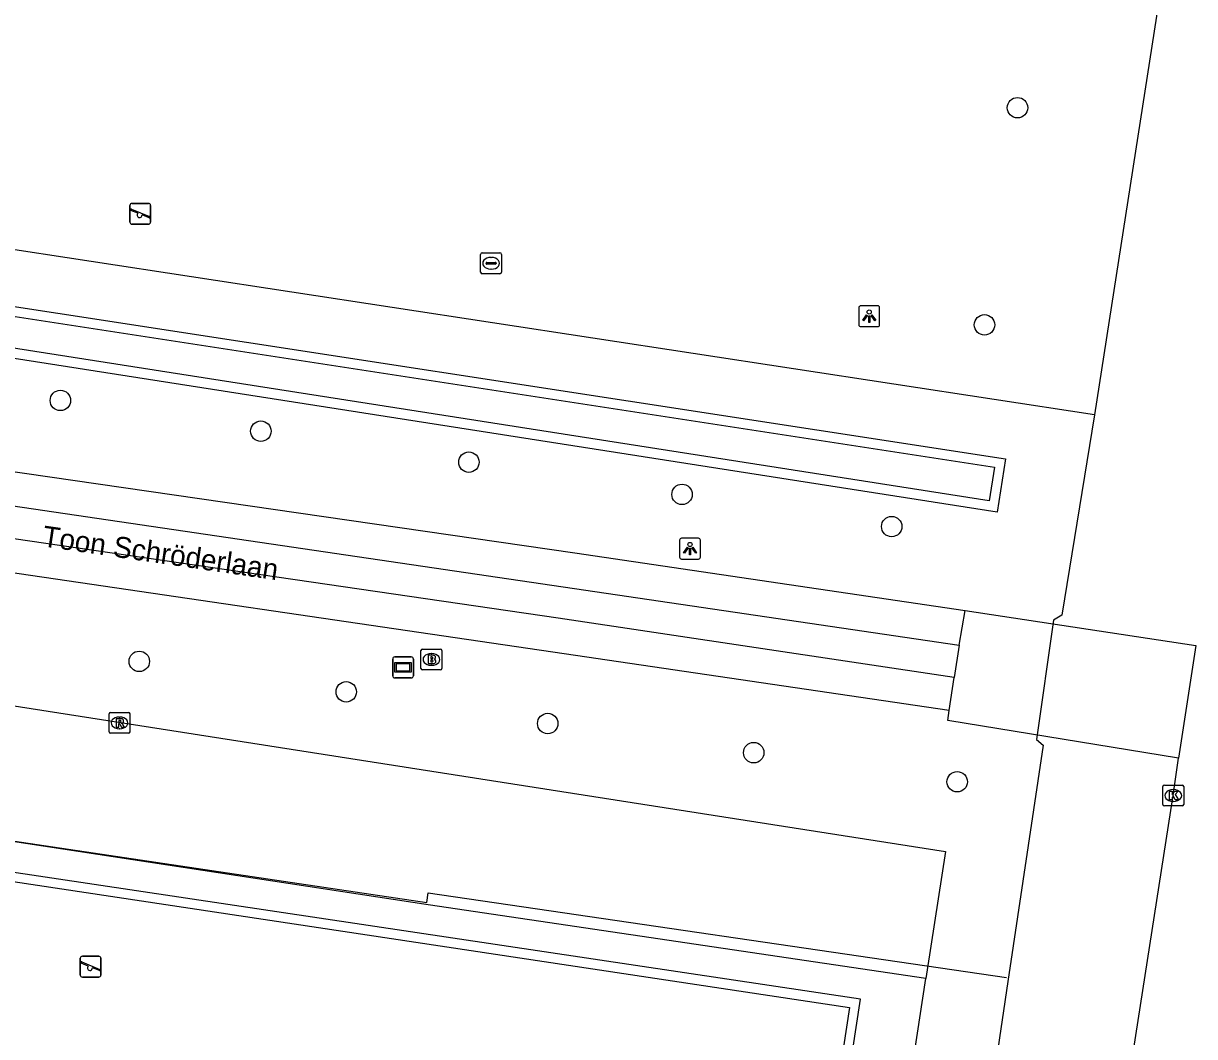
# Model space of a CAD drawing. Extents: x 161094 to 161705, y 379509 to 380907.
# Drawn here: x 161507.4 to 161563.4, y 380124 to 380172.4 of the extents above; entities that cross this region are included whole.
import ezdxf

# ---------------------------------------------------------------- set-up
doc = ezdxf.new("R2010")
doc.units = 0
for name, color, linetype in [('IMGEO_Boom', 7, 'Continuous'), ('IMGEO_Brandkraan', 7, 'Continuous'), ('IMGEO_Greppel_droge_sloot', 7, 'Continuous'), ('IMGEO_Groenvoorziening', 7, 'Continuous'), ('IMGEO_Hek', 7, 'Continuous'), ('IMGEO_Kolk', 7, 'Continuous'), ('IMGEO_Lichtpunt', 7, 'Continuous'), ('IMGEO_Openbare_ruimte_label', 7, 'Continuous'), ('IMGEO_OVBaan_gesloten', 7, 'Continuous'), ('IMGEO_Rijbaan_lokaal_gesloten', 7, 'Continuous'), ('IMGEO_Rijbaan_lokaal_open', 7, 'Continuous'), ('IMGEO_Rioolput', 7, 'Continuous'), ('IMGEO_Speelvoorziening', 7, 'Continuous'), ('IMGEO_Verklikker', 7, 'Continuous'), ('IMGEO_Voetpad_open', 7, 'Continuous'), ('IMGEO_Waterleidingput', 7, 'Continuous')]:
    doc.layers.add(name, color=color, linetype=linetype)

msp = doc.modelspace()

# ---------------------------------------------------------------- linework, layer by layer
at = {"layer": 'IMGEO_Boom'}
for centre in [(161554.975, 380168.413), (161553.395, 380158.024), (161509.163, 380154.409), (161518.76, 380152.937), (161528.716, 380151.457), (161538.917, 380149.914), (161548.952, 380148.375), (161512.94, 380141.927), (161522.845, 380140.47), (161532.489, 380138.953), (161542.348, 380137.559), (161552.088, 380136.168)]:
    msp.add_circle(centre, 0.489, dxfattribs=at)
at = {"layer": 'IMGEO_Brandkraan'}
for p, q in [((161526.422, 380141.592), (161526.422, 380142.444)), ((161526.497, 380142.518), (161527.349, 380142.518)), ((161526.91, 380142.298), (161526.935, 380142.298)), ((161527.423, 380142.444), (161527.423, 380141.592)), ((161526.933, 380141.738), (161526.908, 380141.738)), ((161527.349, 380141.518), (161526.497, 380141.518))]:
    msp.add_line(p, q, dxfattribs=at)
for points in [[(161526.422, 380141.592), (161526.422, 380142.444)], [(161526.497, 380142.518), (161527.349, 380142.518)], [(161527.423, 380142.444), (161527.423, 380141.592)], [(161526.77, 380142.218), (161526.77, 380141.818), (161526.983, 380141.818)], [(161527.001, 380142.218), (161526.77, 380142.218)], [(161526.949, 380142.137), (161526.895, 380142.137), (161526.895, 380142.061)], [(161526.895, 380142.061), (161526.948, 380142.061)], [(161526.957, 380141.985), (161526.895, 380141.985), (161526.895, 380141.904)], [(161526.895, 380141.904), (161526.957, 380141.904)], [(161527.349, 380141.518), (161526.497, 380141.518)]]:
    msp.add_lwpolyline(points, dxfattribs=at)
for centre, radius, start, end in [((161526.499, 380142.442), 0.0765, 91.552, 178.448), ((161526.499, 380142.442), 0.0765, 91.552, 178.448), ((161527.347, 380142.442), 0.0765, 1.552, 88.448), ((161527.347, 380142.442), 0.0765, 1.552, 88.448), ((161526.95, 380142.099), 0.0379, 267.8285, 90.9355), ((161526.958, 380141.944), 0.0404, 269.8759, 90.5077), ((161526.989, 380142.069), 0.251, 268.6676, 293.5347), ((161527.005, 380142.073), 0.145, 59.4692, 91.5367), ((161527.03, 380142.12), 0.0922, 285.5137, 58.1501), ((161527.035, 380141.928), 0.105, 301.3115, 78.989), ((161526.499, 380141.594), 0.0765, 181.552, 268.448), ((161526.499, 380141.594), 0.0765, 181.552, 268.448), ((161527.347, 380141.594), 0.0765, 271.552, 358.448), ((161527.347, 380141.594), 0.0765, 271.552, 358.448)]:
    msp.add_arc(centre, radius, start, end, dxfattribs=at)
for centre, major_axis, ratio, start_param, end_param in [((161526.909, 380142.018), (-0.387, 0.002), 0.722429, 4.712389, 7.853982), ((161526.934, 380142.018), (-0.39, 0.002), 0.717154, 1.570796, 4.712389)]:
    msp.add_ellipse(centre, major_axis=major_axis, ratio=ratio, start_param=start_param, end_param=end_param, dxfattribs=at)
at = {"layer": 'IMGEO_Greppel_droge_sloot'}
msp.add_lwpolyline([(161473.065, 380163.338), (161499.931, 380159.506), (161553.869, 380151.216), (161553.617, 380149.602), (161500.075, 380157.97), (161473.828, 380162.362), (161472.907, 380162.528), (161473.065, 380163.338)], dxfattribs=at)
at = {"layer": 'IMGEO_Groenvoorziening'}
for points in [[(161472.69, 380163.865), (161500, 380159.97), (161554.405, 380151.608), (161554.008, 380149.066), (161500, 380157.507), (161473.748, 380161.9), (161472.356, 380162.15)], [(161470.795, 380145.44), (161500, 380140.879), (161551.533, 380132.833), (161550.65, 380127.178), (161550.583, 380126.751)]]:
    msp.add_lwpolyline(points, dxfattribs=at)
at = {"layer": 'IMGEO_Hek'}
for points in [[(161574.717, 380256.895), (161558.655, 380153.718), (161557.098, 380144.137), (161556.703, 380143.895), (161555.891, 380138.191), (161556.195, 380137.916), (161554.512, 380126.608)], [(161558.655, 380153.718), (161472.202, 380166.92), (161467.427, 380173.551), (161469.43, 380186.379), (161475.815, 380227.062), (161478.929, 380247.203)], [(161469.666, 380139.945), (161469.909, 380139.909), (161470.935, 380139.757), (161470.838, 380139.11), (161501.266, 380134.593), (161501.176, 380134.189), (161526.703, 380130.395), (161526.77, 380130.85), (161554.448, 380126.797)], [(161459.798, 380029.532), (161531.163, 380018.876), (161534.934, 380043.376), (161537.395, 380042.998), (161538.44, 380050.25), (161535.99, 380050.634), (161542.6, 380093.986), (161545.043, 380093.588), (161546.157, 380100.79), (161543.702, 380101.148), (161547.462, 380125.77), (161476.115, 380136.431), (161472.333, 380111.821), (161469.879, 380112.192), (161468.777, 380104.974), (161471.226, 380104.631), (161470.057, 380096.97)], [(161554.512, 380126.608), (161529.782, 379959.399)]]:
    msp.add_lwpolyline(points, dxfattribs=at)
at = {"layer": 'IMGEO_Kolk'}
for p, q in [((161561.93, 380135.085), (161561.93, 380135.937)), ((161562.005, 380136.011), (161562.857, 380136.011)), ((161562.418, 380135.791), (161562.443, 380135.791)), ((161562.931, 380135.937), (161562.931, 380135.085)), ((161562.857, 380135.011), (161562.005, 380135.011)), ((161562.441, 380135.231), (161562.416, 380135.231))]:
    msp.add_line(p, q, dxfattribs=at)
for points in [[(161561.93, 380135.085), (161561.93, 380135.937)], [(161562.005, 380136.011), (161562.857, 380136.011)], [(161562.251, 380135.711), (161562.374, 380135.711), (161562.374, 380135.56), (161562.504, 380135.711), (161562.668, 380135.711), (161562.522, 380135.56), (161562.675, 380135.311), (161562.523, 380135.311), (161562.438, 380135.475), (161562.374, 380135.408), (161562.374, 380135.311), (161562.251, 380135.311), (161562.251, 380135.711)], [(161562.931, 380135.937), (161562.931, 380135.085)], [(161562.857, 380135.011), (161562.005, 380135.011)]]:
    msp.add_lwpolyline(points, dxfattribs=at)
for centre, start, end in [((161562.007, 380135.935), 91.552, 178.448), ((161562.007, 380135.935), 91.552, 178.448), ((161562.855, 380135.935), 1.552, 88.448), ((161562.855, 380135.935), 1.552, 88.448), ((161562.007, 380135.087), 181.552, 268.448), ((161562.007, 380135.087), 181.552, 268.448), ((161562.855, 380135.087), 271.552, 358.448), ((161562.855, 380135.087), 271.552, 358.448)]:
    msp.add_arc(centre, 0.0765, start, end, dxfattribs=at)
for centre, major_axis, ratio, start_param, end_param in [((161562.417, 380135.511), (-0.387, 0.002), 0.722429, 4.712389, 7.853982), ((161562.442, 380135.511), (-0.39, 0.002), 0.717154, 1.570796, 4.712389)]:
    msp.add_ellipse(centre, major_axis=major_axis, ratio=ratio, start_param=start_param, end_param=end_param, dxfattribs=at)
at = {"layer": 'IMGEO_Lichtpunt'}
for p, q in [((161547.379, 380158.843), (161547.379, 380158.036)), ((161547.379, 380158.843), (161547.379, 380158.036)), ((161548.281, 380158.938), (161547.473, 380158.938)), ((161548.281, 380158.938), (161547.473, 380158.938)), ((161548.375, 380158.036), (161548.375, 380158.843)), ((161548.375, 380158.036), (161548.375, 380158.843)), ((161547.473, 380157.942), (161548.281, 380157.942)), ((161547.473, 380157.942), (161548.281, 380157.942)), ((161538.803, 380147.723), (161538.803, 380146.916)), ((161538.803, 380147.723), (161538.803, 380146.916)), ((161539.705, 380147.818), (161538.897, 380147.818)), ((161539.705, 380147.818), (161538.897, 380147.818)), ((161539.799, 380146.916), (161539.799, 380147.723)), ((161539.799, 380146.916), (161539.799, 380147.723)), ((161538.897, 380146.822), (161539.705, 380146.822)), ((161538.897, 380146.822), (161539.705, 380146.822))]:
    msp.add_line(p, q, dxfattribs=at)
for points in [[(161547.753, 380158.507), (161547.792, 380158.479), (161547.604, 380158.217), (161547.566, 380158.244), (161547.753, 380158.507)], [(161547.965, 380158.479), (161548.003, 380158.506), (161548.19, 380158.244), (161548.151, 380158.216), (161547.965, 380158.479)], [(161547.855, 380158.459), (161547.902, 380158.459), (161547.902, 380158.137), (161547.855, 380158.137), (161547.855, 380158.459)], [(161539.177, 380147.387), (161539.216, 380147.359), (161539.028, 380147.097), (161538.99, 380147.124), (161539.177, 380147.387)], [(161539.279, 380147.339), (161539.326, 380147.339), (161539.326, 380147.017), (161539.279, 380147.017), (161539.279, 380147.339)], [(161539.389, 380147.359), (161539.427, 380147.386), (161539.614, 380147.124), (161539.575, 380147.096), (161539.389, 380147.359)]]:
    msp.add_lwpolyline(points, dxfattribs=at)
for centre in [(161547.878, 380158.641), (161539.302, 380147.521)]:
    msp.add_circle(centre, 0.0994, dxfattribs=at)
for centre, start, end in [((161547.473, 380158.843), 90, 180), ((161547.473, 380158.843), 90, 180), ((161548.281, 380158.843), 0, 90), ((161548.281, 380158.843), 0, 90), ((161547.473, 380158.036), 180, 270), ((161547.473, 380158.036), 180, 270), ((161548.281, 380158.036), 270, 0), ((161548.281, 380158.036), 270, 360), ((161538.897, 380147.723), 90, 180), ((161538.897, 380147.723), 90, 180), ((161539.705, 380147.723), 0, 90), ((161539.705, 380147.723), 0, 90), ((161538.897, 380146.916), 180, 270), ((161538.897, 380146.916), 180, 270), ((161539.705, 380146.916), 270, 0), ((161539.705, 380146.916), 270, 360)]:
    msp.add_arc(centre, 0.0946, start, end, dxfattribs=at)
at = {"layer": 'IMGEO_OVBaan_gesloten'}
for points in [[(161563.514, 380142.679), (161562.682, 380137.292)], [(161534.566, 379947.954), (161535.873, 379956.523), (161536.498, 379960.739), (161537.983, 379971.128), (161539.551, 379981.976), (161540.995, 379992.261), (161542.476, 380003.246), (161545.369, 380024.521), (161547.158, 380036.592), (161548.98, 380048.715), (161552.247, 380069.932), (161555.56, 380091.102), (161558.658, 380111.326), (161562.431, 380135.511), (161562.682, 380137.292)]]:
    msp.add_lwpolyline(points, dxfattribs=at)
at = {"layer": 'IMGEO_Rijbaan_lokaal_gesloten'}
for points in [[(161471.287, 380156.48), (161486.998, 380153.95), (161505.002, 380151.276), (161533.779, 380147.123), (161552.468, 380144.356)], [(161551.948, 380141.154), (161532.99, 380143.989), (161504.507, 380148.144), (161486.372, 380150.902), (161471.474, 380153.186), (161464.019, 380154.384), (161464.235, 380155.875), (161471.842, 380154.694), (161486.778, 380152.4), (161504.718, 380149.687), (161533.226, 380145.488), (161552.181, 380142.696)], [(161551.698, 380139.577), (161532.737, 380142.374), (161504.241, 380146.538), (161486.012, 380149.348), (161471.762, 380151.473)], [(161552.181, 380142.696), (161552.468, 380144.356)], [(161551.698, 380139.577), (161551.948, 380141.154)]]:
    msp.add_lwpolyline(points, dxfattribs=at)
at = {"layer": 'IMGEO_Rijbaan_lokaal_open'}
for points in [[(161552.468, 380144.356), (161563.514, 380142.679)], [(161552.181, 380142.696), (161551.948, 380141.154)], [(161562.682, 380137.292), (161551.641, 380139.098), (161551.698, 380139.577)]]:
    msp.add_lwpolyline(points, dxfattribs=at)
at = {"layer": 'IMGEO_Rioolput'}
for p, q in [((161511.57, 380139.485), (161512.422, 380139.485)), ((161511.495, 380138.559), (161511.495, 380139.411)), ((161511.983, 380139.265), (161512.008, 380139.265)), ((161512.496, 380139.411), (161512.496, 380138.559)), ((161512.422, 380138.485), (161511.57, 380138.485)), ((161512.006, 380138.705), (161511.981, 380138.705))]:
    msp.add_line(p, q, dxfattribs=at)
for points in [[(161511.57, 380139.485), (161512.422, 380139.485)], [(161511.495, 380138.559), (161511.495, 380139.411)], [(161512.084, 380139.183), (161511.832, 380139.185), (161511.832, 380138.785)], [(161511.832, 380138.785), (161511.956, 380138.785), (161511.956, 380138.947), (161511.967, 380138.947)], [(161512.01, 380139.104), (161511.956, 380139.104), (161511.956, 380139.023)], [(161511.956, 380139.023), (161512.008, 380139.023)], [(161512.014, 380138.918), (161512.085, 380138.785), (161512.225, 380138.785), (161512.16, 380138.911)], [(161512.496, 380139.411), (161512.496, 380138.559)], [(161512.422, 380138.485), (161511.57, 380138.485)]]:
    msp.add_lwpolyline(points, dxfattribs=at)
for centre, radius, start, end in [((161511.572, 380139.409), 0.0765, 91.552, 178.448), ((161511.572, 380139.409), 0.0765, 91.552, 178.448), ((161512.42, 380139.409), 0.0765, 1.552, 88.448), ((161512.42, 380139.409), 0.0765, 1.552, 88.448), ((161511.966, 380138.894), 0.0533, 26.0293, 88.6989), ((161511.992, 380139.212), 0.19, 274.7715, 282.9687), ((161512.016, 380139.008), 0.0964, 77.0061, 93.1865), ((161512.03, 380139.065), 0.0378, 276.6634, 79.6772), ((161512.083, 380139.073), 0.109, 350.3612, 89.416), ((161512.081, 380139.073), 0.112, 277.5842, 350.9817), ((161512.065, 380138.858), 0.108, 29.5134, 73.7905), ((161511.572, 380138.561), 0.0765, 181.552, 268.448), ((161511.572, 380138.561), 0.0765, 181.552, 268.448), ((161512.42, 380138.561), 0.0765, 271.552, 358.448), ((161512.42, 380138.561), 0.0765, 271.552, 358.448)]:
    msp.add_arc(centre, radius, start, end, dxfattribs=at)
for centre, major_axis, ratio, start_param, end_param in [((161511.982, 380138.985), (-0.387, 0.002), 0.722429, 4.712389, 7.853982), ((161512.007, 380138.985), (-0.39, 0.002), 0.717154, 1.570796, 4.712389)]:
    msp.add_ellipse(centre, major_axis=major_axis, ratio=ratio, start_param=start_param, end_param=end_param, dxfattribs=at)
at = {"layer": 'IMGEO_Speelvoorziening'}
for p, q in [((161512.491, 380162.937), (161512.491, 380163.737)), ((161512.491, 380163.737), (161512.491, 380162.937)), ((161512.56, 380163.562), (161513.436, 380163.209)), ((161512.591, 380163.837), (161513.381, 380163.837)), ((161513.381, 380163.837), (161512.591, 380163.837)), ((161513.481, 380163.737), (161513.481, 380162.937)), ((161513.481, 380162.937), (161513.481, 380163.737)), ((161512.874, 380163.365), (161512.535, 380163.502)), ((161513.412, 380163.149), (161513.072, 380163.286)), ((161513.381, 380162.837), (161512.591, 380162.837)), ((161512.591, 380162.837), (161513.381, 380162.837)), ((161510.115, 380126.922), (161510.115, 380127.722)), ((161510.115, 380127.722), (161510.115, 380126.922)), ((161510.215, 380127.822), (161511.005, 380127.822)), ((161511.005, 380127.822), (161510.215, 380127.822)), ((161511.105, 380127.722), (161511.105, 380126.922)), ((161511.105, 380126.922), (161511.105, 380127.722)), ((161510.498, 380127.35), (161510.159, 380127.487)), ((161510.184, 380127.547), (161511.06, 380127.194)), ((161511.036, 380127.134), (161510.696, 380127.271)), ((161511.005, 380126.822), (161510.215, 380126.822)), ((161510.215, 380126.822), (161511.005, 380126.822))]:
    msp.add_line(p, q, dxfattribs=at)
for centre, radius, start, end in [((161512.591, 380163.737), 0.1, 90, 180), ((161512.591, 380163.737), 0.1, 90, 180), ((161512.548, 380163.532), 0.0327, 68.078, 248.078), ((161513.381, 380163.737), 0.1, 0, 90), ((161513.381, 380163.737), 0.1, 360, 90), ((161512.953, 380163.275), 0.12, 130.9928, 5.1632), ((161513.424, 380163.179), 0.0327, 248.078, 68.078), ((161512.591, 380162.937), 0.1, 180, 270), ((161512.591, 380162.937), 0.1, 180, 270), ((161513.381, 380162.937), 0.1, 270, 0), ((161513.381, 380162.937), 0.1, 270, 0), ((161510.215, 380127.722), 0.1, 90, 180), ((161510.215, 380127.722), 0.1, 90, 180), ((161511.005, 380127.722), 0.1, 0, 90), ((161511.005, 380127.722), 0.1, 360, 90), ((161510.172, 380127.517), 0.0327, 68.078, 248.078), ((161510.577, 380127.26), 0.12, 130.9928, 5.1632), ((161511.048, 380127.164), 0.0327, 248.078, 68.078), ((161510.215, 380126.922), 0.1, 180, 270), ((161510.215, 380126.922), 0.1, 180, 270), ((161511.005, 380126.922), 0.1, 270, 0), ((161511.005, 380126.922), 0.1, 270, 0)]:
    msp.add_arc(centre, radius, start, end, dxfattribs=at)
at = {"layer": 'IMGEO_Verklikker'}
for p, q in [((161525.069, 380141.236), (161525.069, 380142.036)), ((161525.069, 380142.036), (161525.069, 380141.236)), ((161525.169, 380142.136), (161525.959, 380142.136)), ((161525.959, 380142.136), (161525.169, 380142.136)), ((161526.059, 380142.036), (161526.059, 380141.236)), ((161526.059, 380141.236), (161526.059, 380142.036)), ((161525.959, 380141.136), (161525.169, 380141.136)), ((161525.169, 380141.136), (161525.959, 380141.136))]:
    msp.add_line(p, q, dxfattribs=at)
for points in [[(161525.17, 380141.868), (161525.958, 380141.868), (161525.958, 380141.404), (161525.17, 380141.404), (161525.17, 380141.868)], [(161525.235, 380141.803), (161525.235, 380141.469), (161525.893, 380141.469), (161525.893, 380141.803), (161525.235, 380141.803)]]:
    msp.add_lwpolyline(points, dxfattribs=at)
for centre, start, end in [((161525.169, 380142.036), 90, 180), ((161525.169, 380142.036), 90, 180), ((161525.959, 380142.036), 0, 90), ((161525.959, 380142.036), 360, 90), ((161525.169, 380141.236), 180, 270), ((161525.169, 380141.236), 180, 270), ((161525.959, 380141.236), 270, 0), ((161525.959, 380141.236), 270, 0)]:
    msp.add_arc(centre, 0.1, start, end, dxfattribs=at)
at = {"layer": 'IMGEO_Voetpad_open'}
for points in [[(161550.583, 380126.751), (161526.76, 380130.285), (161500.889, 380134.218), (161476.394, 380137.909), (161471.178, 380138.695)], [(161476.501, 380135.966), (161546.934, 380125.374), (161530.75, 380019.421), (161460.459, 380030.026), (161460.682, 380032.191), (161476.501, 380135.966)], [(161533.851, 380017.034), (161550.583, 380126.751)]]:
    msp.add_lwpolyline(points, dxfattribs=at)
at = {"layer": 'IMGEO_Waterleidingput'}
for p, q in [((161529.277, 380160.544), (161529.277, 380161.396)), ((161529.352, 380161.47), (161530.204, 380161.47)), ((161530.278, 380161.396), (161530.278, 380160.544)), ((161529.536, 380160.964), (161529.536, 380160.976)), ((161529.974, 380160.927), (161529.576, 380160.927)), ((161529.579, 380161.013), (161529.977, 380161.013)), ((161529.765, 380161.25), (161529.79, 380161.25)), ((161530.02, 380160.976), (161530.02, 380160.964)), ((161530.204, 380160.47), (161529.352, 380160.47)), ((161529.788, 380160.69), (161529.763, 380160.69))]:
    msp.add_line(p, q, dxfattribs=at)
for points in [[(161529.277, 380160.544), (161529.277, 380161.396)], [(161529.352, 380161.47), (161530.204, 380161.47)], [(161530.278, 380161.396), (161530.278, 380160.544)], [(161530.204, 380160.47), (161529.352, 380160.47)]]:
    msp.add_lwpolyline(points, dxfattribs=at)
for centre, radius, start, end in [((161529.354, 380161.394), 0.0765, 91.552, 178.448), ((161529.354, 380161.394), 0.0765, 91.552, 178.448), ((161530.202, 380161.394), 0.0765, 1.552, 88.448), ((161530.202, 380161.394), 0.0765, 1.552, 88.448), ((161529.576, 380160.973), 0.0403, 85.8775, 175.7526), ((161529.573, 380160.963), 0.0366, 178.938, 274.7102), ((161529.977, 380160.97), 0.043, 264.8664, 352.4533), ((161529.981, 380160.975), 0.0386, 1.7309, 96.639), ((161529.354, 380160.546), 0.0765, 181.552, 268.448), ((161529.354, 380160.546), 0.0765, 181.552, 268.448), ((161530.202, 380160.546), 0.0765, 271.552, 358.448), ((161530.202, 380160.546), 0.0765, 271.552, 358.448)]:
    msp.add_arc(centre, radius, start, end, dxfattribs=at)
for centre, major_axis, ratio, start_param, end_param in [((161529.764, 380160.97), (-0.387, 0.002), 0.722429, 4.712389, 7.853982), ((161529.789, 380160.97), (-0.39, 0.002), 0.717154, 1.570796, 4.712389)]:
    msp.add_ellipse(centre, major_axis=major_axis, ratio=ratio, start_param=start_param, end_param=end_param, dxfattribs=at)

# ---------------------------------------------------------------- texts
at = {"layer": 'IMGEO_Openbare_ruimte_label'}
msp.add_text('Toon Schröderlaan', height=1, rotation=351.7808, dxfattribs=at).set_placement((161508.258, 380147.434))

doc.saveas('drawing.dxf')
